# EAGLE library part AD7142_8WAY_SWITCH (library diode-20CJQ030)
AD7142_8WAY_SWITCH is capacitive landpattern for the 8-way button sensor of the AD7142, The 8-way switch is made from two pairs of differential buttons. It, therefore, requires two conversion stages, one for each of the differential button pairs. The buttons are orientated so that one pair makes up the top and bottom portions of the 8-way switch; the other pair makes up the left and right portions of the 8-way switch. Please send any comments to: messi@users.sourceforge.net
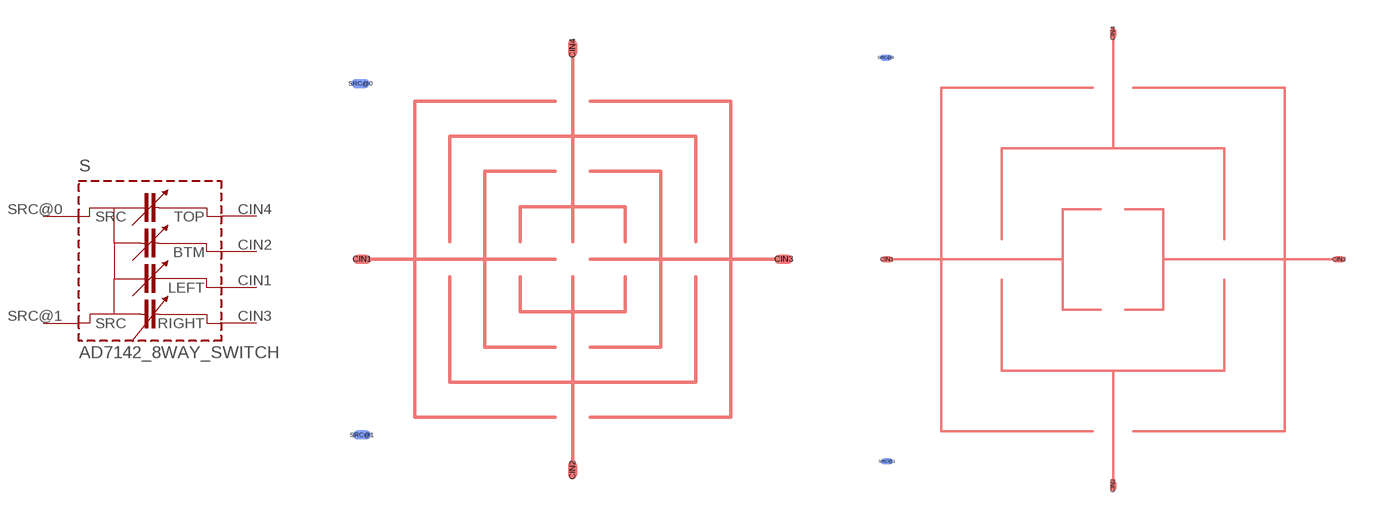
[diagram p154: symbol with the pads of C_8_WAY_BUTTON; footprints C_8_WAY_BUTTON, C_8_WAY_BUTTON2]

Designator prefix S

## AD7142_8WAY_SWITCH-A  [C_8_WAY_BUTTON]
CIN1  LEFT  pas
CIN2  BTM  pas
CIN3  RIGHT  pas
CIN4  TOP  pas
SRC@0  SRC  pas
SRC@1  SRC  pas

## AD7142_8WAY_SWITCH-C  [C_8_WAY_BUTTON2]
Pads as for C_8_WAY_BUTTON

## AD7142_8WAY_SWITCH-B  [C_8_WAY_BUTTON1]
Pads as for C_8_WAY_BUTTON

## Footprint C_8_WAY_BUTTON (pad centres in mm)
Capacitive 8-way button for the AD7142, 12mm by 12mm
smd 0.61 x 0.305: CIN1 -7.2,0; CIN3 7.2,0
smd 0.305 x 0.61: CIN2 0,-7.2; CIN4 0,7.2
smd 0.61 x 0.305 bottom: SRC@0 -7.25,6; SRC@1 -7.2,-6

## Footprint C_8_WAY_BUTTON2 (pad centres in mm)
8 way capacitive button for the AD7142 from Analog Devices, 20mm diameter
smd 0.61 x 0.305: CIN1 -11.2,0; CIN3 11.2,0
smd 0.305 x 0.61: CIN2 0,-11.2; CIN4 0,11.2
smd 0.61 x 0.305 bottom: SRC@0 -11.25,10; SRC@1 -11.2,-10

## Footprint C_8_WAY_BUTTON1 (pad centres in mm)
Capacitive 8-way button for the AD7142, 16.8mm by 16.8mm
smd 0.61 x 0.305: CIN1 -9.6,0; CIN3 9.6,0
smd 0.305 x 0.61: CIN2 0,-9.6; CIN4 0,9.6
smd 0.61 x 0.305 bottom: SRC@0 -9.65,8.4; SRC@1 -9.6,-8.4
